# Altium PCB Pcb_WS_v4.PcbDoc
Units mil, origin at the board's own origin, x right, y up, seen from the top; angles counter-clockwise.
Board outline 3937.01 x 3937.01 mil, 2 copper layers (Top Layer, Bottom Layer); 75 components, 61 nets, 248 pads, 72 vias.
Unrouted connection lines stored in the file: 188.
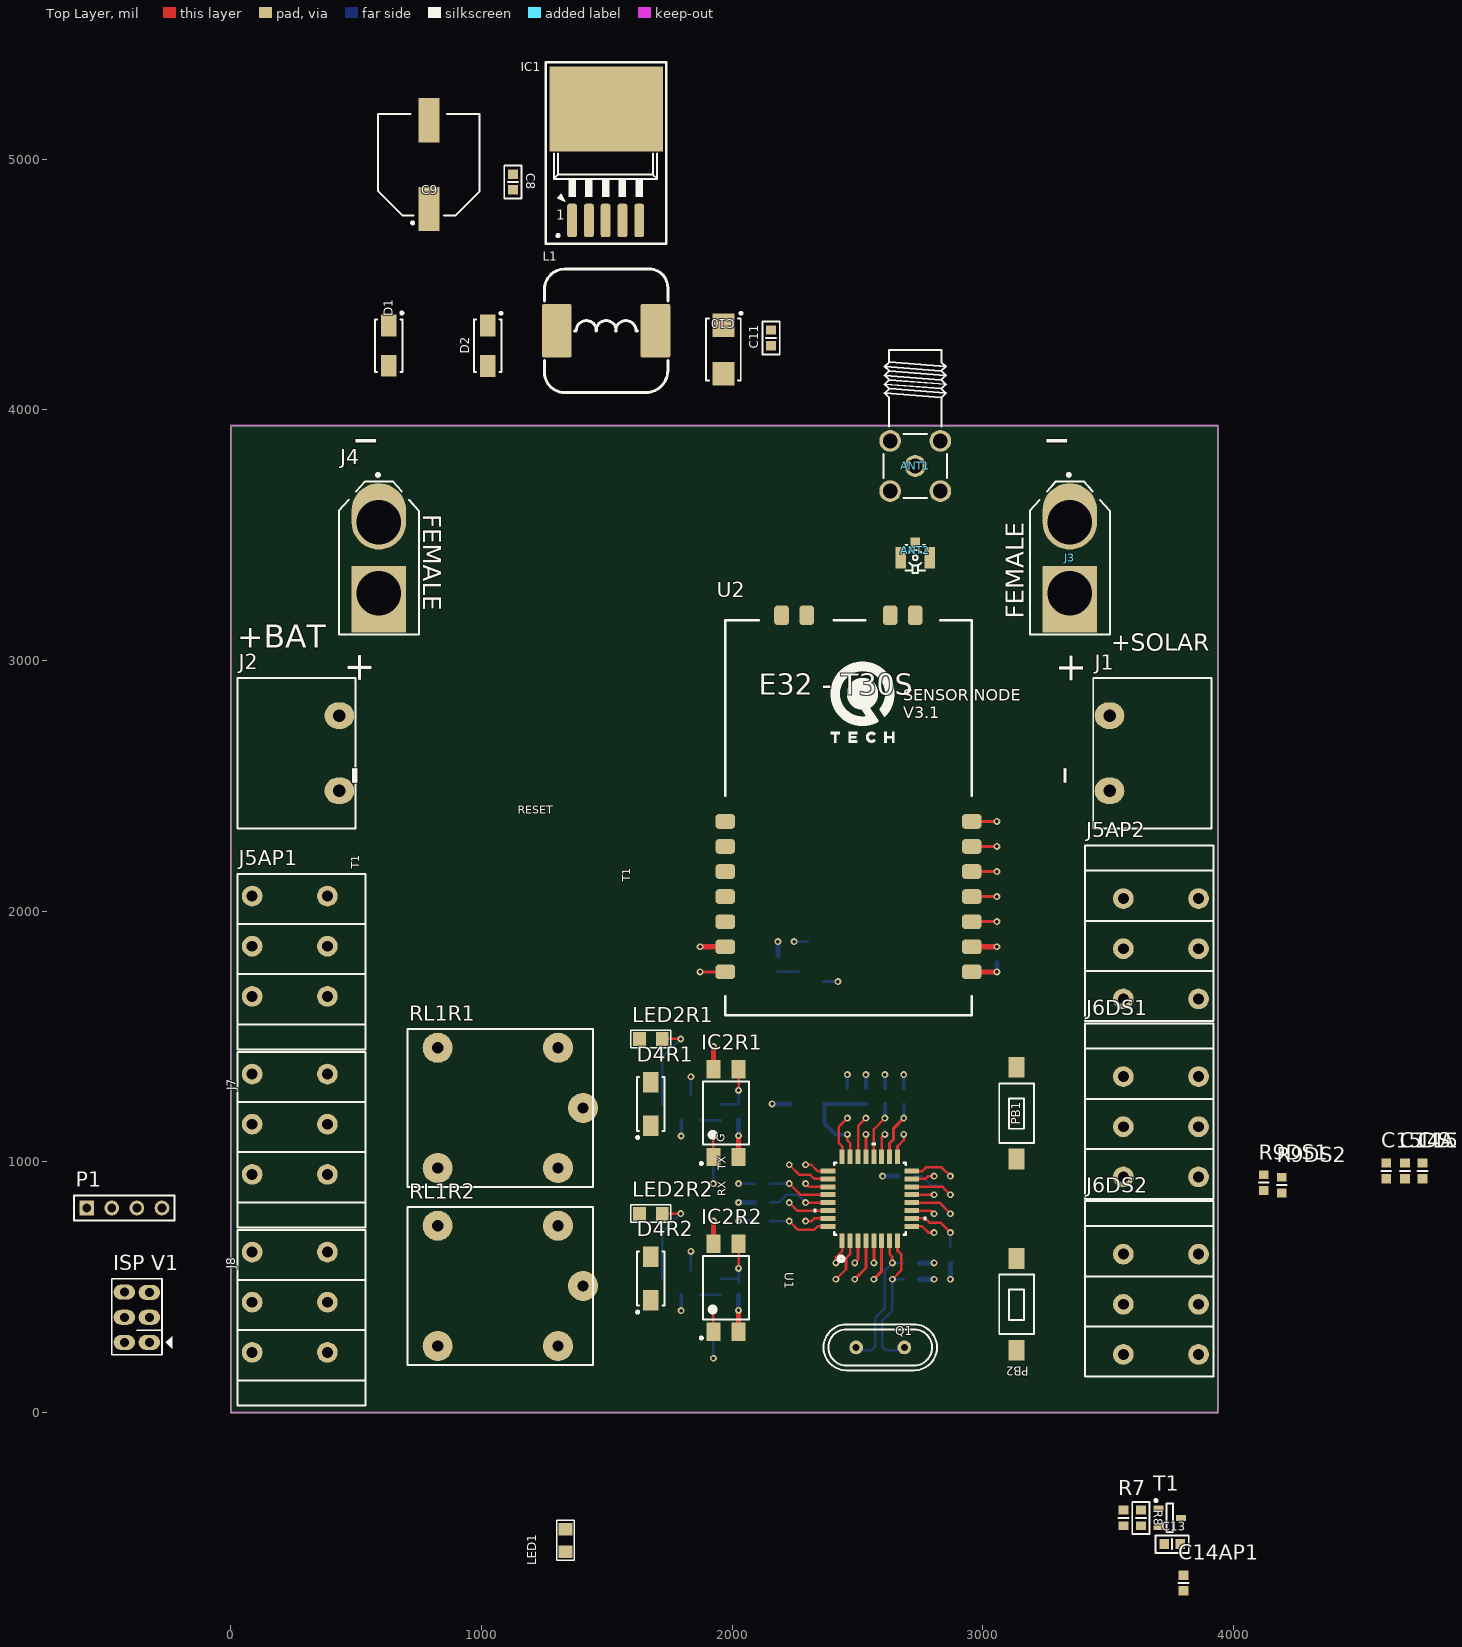
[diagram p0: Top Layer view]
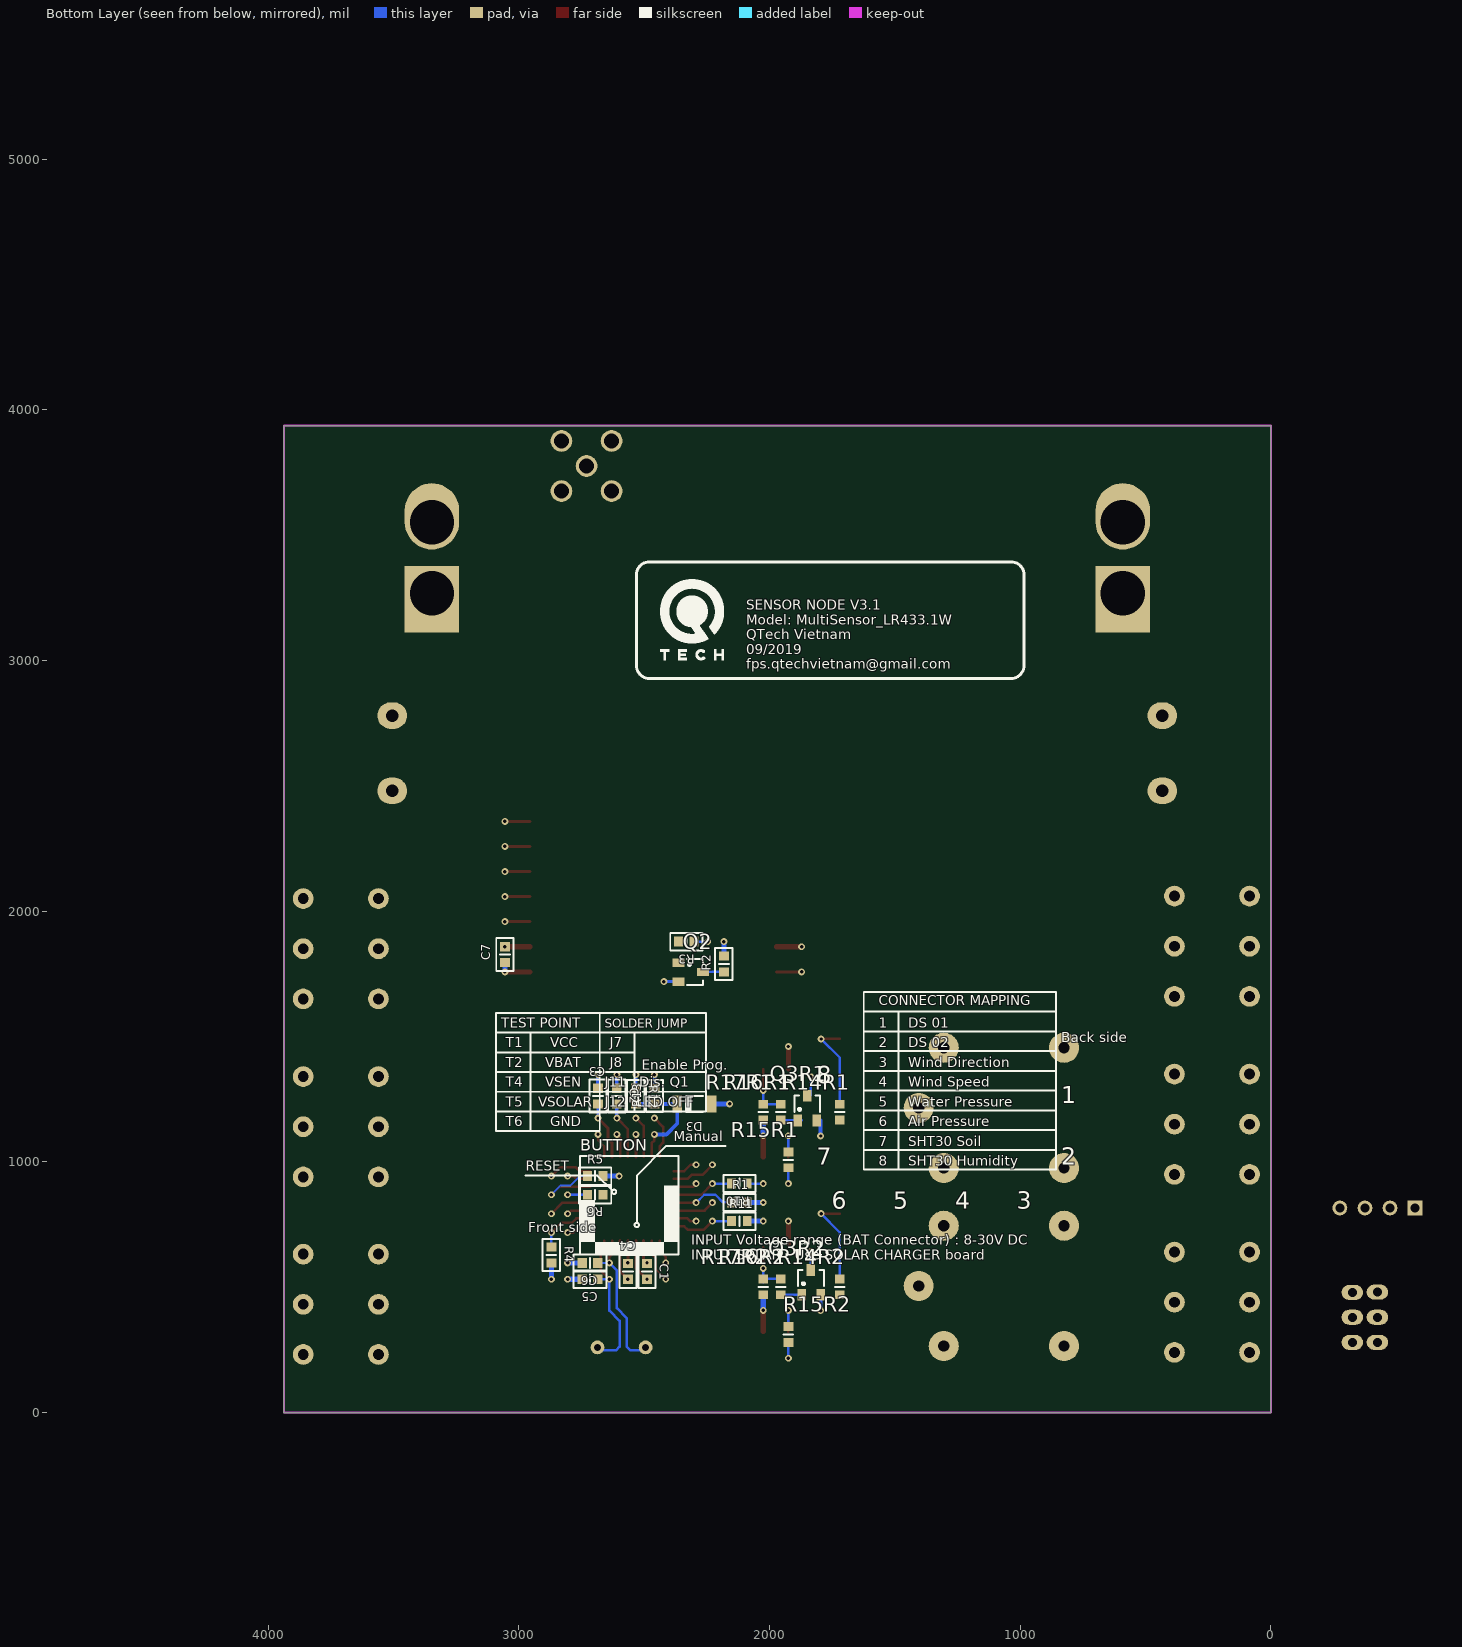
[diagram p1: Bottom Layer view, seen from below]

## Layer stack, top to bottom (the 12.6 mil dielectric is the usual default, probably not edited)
Top Solder: solder mask 0.4, Solder Resist, Dk 3.5
Top Layer: signal copper 1.4
Dielectric 1: dielectric 12.6, FR-4, Dk 4.8
Bottom Layer: signal copper 1.4
Bottom Solder: solder mask 0.4, Solder Resist, Dk 3.5

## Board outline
0,0 0,3937.01 3937.01,3937.01 3937.01,0

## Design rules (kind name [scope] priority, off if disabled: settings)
Clearance [All] p1: gap=7 ignorepadtopadclearanceinfootprint=FALSE
ComponentClearance KF-conn_Clearance [InComponentClass('KF_conn') vs InComponentClass('KF_conn')] p1: gap=5 collisioncheckmode=3 verticalgap=0 showdistances=FALSE
ComponentClearance HS_Comp_Clearance [InComponentClass('HS_Comp') vs IsComponent] p2: gap=175 collisioncheckmode=3 verticalgap=0 showdistances=FALSE
ComponentClearance IC_Comp_Clearance [InComponentClass('IC_Comp') vs IsComponent] p3: gap=150 collisioncheckmode=3 verticalgap=0 showdistances=FALSE
ComponentClearance conn-th_Clearance [InComponentClass('conn-th') vs IsComponent and not InComponentClass('conn-th')] p4: gap=150 collisioncheckmode=3 verticalgap=250 showdistances=FALSE
ComponentClearance chip-ge_Clearance [InComponentClass('chip-ge') vs InAnyComponent] p5: gap=100 collisioncheckmode=3 verticalgap=0 showdistances=FALSE
ComponentClearance chip-0603_Clearance [InComponentClass('chip-0603') vs IsComponent] p6: gap=25 collisioncheckmode=3 verticalgap=0 showdistances=FALSE
PolygonConnect [All] p1: thpad.connectstyle=Relief thpad.reliefconductorwidth=13.78 thpad.reliefentries=4 thpad.polygonreliefangle="45 Angle" thpad.airgapwidth=10 smdpad.connectstyle=Relief smdpad.reliefconductorwidth=11.81 smdpad.reliefentries=4 smdpad.polygonreliefangle="45 Angle" smdpad.airgapwidth=10 via.connectstyle=Direct via.reliefconductorwidth=10 via.reliefentries=4 via.polygonreliefangle="90 Angle" via.airgapwidth=10
RoomDefinition Top_Level [InComponentClass('Top_Level')] p1: confinementstyle=ConfineIn formatcopy=TRUE lockcomponents=FALSE outline -1380,-1215 620,-1215 620,-215 -1380,-215
RoomDefinition R2 [InComponentClass('R2')] p2: confinementstyle=ConfineIn formatcopy=TRUE lockcomponents=FALSE outline -1380,-1215 620,-1215 620,-215 -1380,-215
RoomDefinition R1 [InComponentClass('R1')] p3: confinementstyle=ConfineIn formatcopy=TRUE lockcomponents=FALSE outline -1380,-1215 620,-1215 620,-215 -1380,-215
RoomDefinition PWR [InComponentClass('PWR')] p4: confinementstyle=ConfineIn formatcopy=TRUE lockcomponents=FALSE outline -1380,-1215 620,-1215 620,-215 -1380,-215
RoomDefinition Main [InComponentClass('Main')] p5: confinementstyle=ConfineIn formatcopy=TRUE lockcomponents=FALSE outline -1380,-1215 620,-1215 620,-215 -1380,-215
RoomDefinition Lora [InComponentClass('Lora')] p6: confinementstyle=ConfineIn formatcopy=TRUE lockcomponents=FALSE outline -1380,-1215 620,-1215 620,-215 -1380,-215
RoomDefinition DS2 [InComponentClass('DS2')] p7: confinementstyle=ConfineIn formatcopy=TRUE lockcomponents=FALSE outline -1380,-1215 620,-1215 620,-215 -1380,-215
RoomDefinition DS1 [InComponentClass('DS1')] p8: confinementstyle=ConfineIn formatcopy=TRUE lockcomponents=FALSE outline -1380,-1215 620,-1215 620,-215 -1380,-215
RoomDefinition AP2 [InComponentClass('AP2')] p9: confinementstyle=ConfineIn formatcopy=TRUE lockcomponents=FALSE outline -1380,-1215 620,-1215 620,-215 -1380,-215
RoomDefinition AP1 [InComponentClass('AP1')] p10: confinementstyle=ConfineIn formatcopy=TRUE lockcomponents=FALSE outline -1380,-1215 620,-1215 620,-215 -1380,-215
RoutingVias [All] p1: holewidth=13.78 width=27.56 viastyle="Through Hole" minholewidth=11.81 minwidth=23.62 maxholewidth=19.68 maxwidth=39.37
ShortCircuit [All] p1: allowed=TRUE
SolderMaskExpansion [All] p1: expansion=4 istentingtop=FALSE
Width [All] p1: maxlimit=196.85 minlimit=8 preferedwidth=10
28 further rules are at their usual default settings.

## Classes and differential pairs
component class KF_conn: J5AP1 J5AP2 J6DS1 J6DS2 J7 J8
component class HS_Comp: ANT1 ANT2 Q1
component class IC_Comp: IC1 IC2R1 IC2R2 L1 U1 U2
component class chip-ge: C9 C10 D1 D2 D4R1 D4R2
component class conn-th: "ISP V1" J1 J2 J3 J4 J5AP1 J5AP2 J6DS1 J6DS2 J7 J8 P1 PB1 PB2 RL1R1 RL1R2
component class chip-0603: C1 C2 C3 C4 C5 C6 C7 C8 C11 C13 C14AP1 C14AP2 C15DS1 C15DS2 D3 LED1 LED2R1 LED2R2 Q2 Q3R1 Q3R2 R1 R2 R3 R4 R5 R6 R7 R8 R9DS1 R9DS2 R10 R11 R12 R13 R14R1 R14R2 R15R1 R15R2 R16R1 R16R2 R17R1 R17R2 T1
channel class Sensor_DS18b20_1Wire: DS1 DS2
channel class Sensor_AirPressure_1Wire: AP1 AP2
channel class Relay: R1 R2
component class Top_Level: D3 J7 J8 LED1 P1 PB2 R10 R11 R12 R13
component class R2: D4R2 IC2R2 LED2R2 Q3R2 R14R2 R15R2 R16R2 R17R2 RL1R2
component class R1: D4R1 IC2R1 LED2R1 Q3R1 R14R1 R15R1 R16R1 R17R1 RL1R1
component class Main: C1 C2 C3 C4 C5 C6 "ISP V1" PB1 Q1 R1 U1
component class Lora: ANT1 ANT2 C7 Q2 R2 R3 R4 R5 R6 U2
component class DS2: C15DS2 J6DS2 R9DS2
component class DS1: C15DS1 J6DS1 R9DS1
component class AP2: C14AP2 J5AP2
component class AP1: C14AP1 J5AP1
component class PWR: C8 C9 C10 C11 C13 D1 D2 IC1 J1 J2 J3 J4 L1 R7 R8 T1

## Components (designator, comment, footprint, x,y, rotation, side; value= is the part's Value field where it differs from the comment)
ANT1 "Coax_1Female_1Shield" "HUBER-SUHNER_85 SMA-50-0-101/111 NE" 2729.98,3775.65 r90 top
ANT2 "U.FL" HIROSE_U.FL-R-SMT-1(10) 2729.98,3409.96 r180 top
C1 "100nF" CAPC1608X87N 2488.75,563.14 r90 bottom
C2 "100nF" CAPC1608X87N 2609.14,1262.28 r270 bottom
C3 "100nF" CAPC1608X87N 2684.14,1262.28 r90 bottom
C4 "100nF" CAPC1608X87N 2564.69,563.14 r90 bottom
C5 "100nF" CAPC1608X87N 2715.95,531.64 r0 bottom value=22pF
C6 "100nF" CAPC1608X87N 2715.95,596.64 r0 bottom value=22pF
C7 "100nF" CAPC1608X87N 3055.57,1826.46 r270 bottom
C8 "100nF" CAPC1608X87N 1125,4908.5 r90 top
C9 "470uF" CAPAE1030X1020N 790,4977.84 r90 top
C10 "100uF" CAPMP6032X280N 1965,4240.24 r270 top
C11 "100nF" CAPC1608X87N 2155,4286.5 r270 top
C13 "100nF" CAPC1608X87N 3755,-524.96 r180 top
C14AP1 "100nF" CAPC1608X87N 3800,-680 r90 top (schematic designator C14)
C14AP2 "100nF" CAPC1608X87N 4684,964 r90 top (schematic designator C14)
C15DS1 "100nF" CAPC1608X87N 4609,964 r90 top (schematic designator C15)
C15DS2 "100nF" CAPC1608X87N 4754,964 r90 top (schematic designator C15)
D1 "SS16" DIOM5127X229N 630,4255.71 r270 top
D2 "SS16" DIOM5127X229N 1025,4255 r270 top
D3 "BZV55-B5V1" DIOMELF3515N 2299.1,1231 r180 bottom
D4R1 "BZG03C220" DIOM5326X230N 1675,1231 r90 top (schematic designator D4)
D4R2 "BZG03C220" DIOM5326X230N 1675,534.27 r90 top (schematic designator D4)
IC1 "LM2596" TO263-5 1361.14,4755 r0 top
IC2R1 "SFH6156-4" SOIC254P977X406-4N 1975,1194.47 r90 top (schematic designator IC2)
IC2R2 "SFH6156-4" SOIC254P977X406-4N 1975,497.74 r90 top (schematic designator IC2)
"ISP V1" "Connector 3x2" JP3x2 -375,380 r90 top
J1 "CON KF7.62-2P" "CON KF7.62-2P" 3505,2630 r270 top
J2 "CON KF7.62-2P" "CON KF7.62-2P" 433.07,2630 r90 top
J3 "XT60-FM" XT60-FM 3346.46,3409.45 r270 top locked
J4 "XT60-FM" XT60-FM 590.55,3409.45 r270 top locked
J5AP1 "KF142V-3P" "CON KF142V-3P-5.08" 85,2060 r270 top (schematic designator J5)
J5AP2 "KF142V-3P" "CON KF142V-3P-5.08" 3860,1650 r90 top (schematic designator J5)
J6DS1 "KF142V-3P" "CON KF142V-3P-5.08" 3860,940 r90 top (schematic designator J6)
J6DS2 "KF142V-3P" "CON KF142V-3P-5.08" 3860,231.72 r90 top (schematic designator J6)
J7 "KF142V-3P" "CON KF142V-3P-5.08" 85,1350 r270 top
J8 "KF142V-3P" "CON KF142V-3P-5.08" 85,640 r270 top
L1 "33uH" L_SMD 1300,4315 r90 top
LED1 "LED" L-0805 1335,-510 r270 top value="LED 3 ly Single Colour"
LED2R1 "LED" L-0805 1675,1490 r180 top value="LED 3 ly Single Colour" (schematic designator LED2)
LED2R2 "LED" L-0805 1675,793.27 r180 top value="LED 3 ly Single Colour" (schematic designator LED2)
P1 "Header 4" HDR1X4 -575,816 r0 top
PB1 "Push Button" PB_TYCO_FSMSM 3134,1194 r270 top
PB2 "Push Button" PB_TYCO_FSMSM 3134,431.72 r270 top
Q1 "20MHz" XTAL_HC-49/U 2590.35,259.85 r0 top
Q2 "C1815" SOT23-3 2314.31,1757.6 r270 bottom
Q3R1 "C1815" SOT23-3 1850,1214.47 r180 bottom (schematic designator Q3)
Q3R2 "C1815" SOT23-3 1835,518.77 r180 bottom (schematic designator Q3)
R1 "10k" RESC1608X55N 2120.35,837.85 r0 bottom
R2 "10k" RESC1608X55N 2182.1,1788.9 r90 bottom value=4k7
R3 "10k" RESC1608X55N 2332.02,1878.19 r0 bottom value=1k
R4 "10k" RESC1608X55N 2870.35,628.5 r90 bottom value=1k
R5 "4k7" RESC1608X55N 2695.31,942.85 r180 bottom value=10k
R6 "4k7" RESC1608X55N 2695.31,868.8 r180 bottom value=10k
R7 "1k" RESC1608X55N 3560,-420 r90 top
R8 "10k" RESC1608X55N 3630,-420 r90 top
R9DS1 "4k7" RESC1608X55N 4120,917 r90 top (schematic designator R9)
R9DS2 "4k7" RESC1608X55N 4192,907 r90 top (schematic designator R9)
R10 "10k" RESC1608X55N 2120.35,913.25 r180 bottom value=200
R11 "10k" RESC1608X55N 2120.35,763.25 r0 bottom
R12 "10k" RESC1608X55N 2533.2,1262.28 r270 bottom value=2M
R13 "10k" RESC1608X55N 2459.14,1262.28 r90 bottom value=1M
R14R1 "1k" RESC1608X55N 1720,1197.98 r90 bottom value=200 (schematic designator R14)
R14R2 "1k" RESC1608X55N 1720,501.24 r90 bottom value=200 (schematic designator R14)
R15R1 "1k" RESC1608X55N 1925,1007.98 r90 bottom (schematic designator R15)
R15R2 "1k" RESC1608X55N 1925,311.24 r90 bottom (schematic designator R15)
R16R1 "1k" RESC1608X55N 1955,1197.98 r270 bottom value=200 (schematic designator R16)
R16R2 "1k" RESC1608X55N 1955,501.24 r270 bottom value=200 (schematic designator R16)
R17R1 "10k" RESC1608X55N 2025,1197.98 r90 bottom (schematic designator R17)
R17R2 "10k" RESC1608X55N 2025,501.24 r90 bottom (schematic designator R17)
RL1R1 "Relay 10A/12V" RL_SPDT_10A 1405,1215 r180 top value="Relay SPDT, 10A, 12V" (schematic designator RL1)
RL1R2 "Relay 10A/12V" RL_SPDT_10A 1405,505 r180 top value="Relay SPDT, 10A, 12V" (schematic designator RL1)
T1 "BSH203" SOT95P230X110-3N 3745,-420 r0 top
U1 "ATmega328-AU" 32A_ATM-M 2548.95,853.05 r90 top
U2 "E32-T30S" E32-T30S 2955.57,3160.31 r180 top

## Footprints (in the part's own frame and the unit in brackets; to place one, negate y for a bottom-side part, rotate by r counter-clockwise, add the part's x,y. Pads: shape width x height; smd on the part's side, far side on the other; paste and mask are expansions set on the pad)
32A_ATM-M [mil]
  rect 58x20 smd: 1(-167,110.24) 2(-167,78.74) 3(-167,47.24) 4(-167,15.75) 5(-167,-15.75) 6(-167,-47.24) 7(-167,-78.74) 8(-167,-110.24) 17(167,-110.24) 18(167,-78.74) 19(167,-47.24) 20(167,-15.75) 21(167,15.75) 22(167,47.24) 23(167,78.74) 24(167,110.24)
  rect 20x58 smd: 9(-110.24,-167) 10(-78.74,-167) 11(-47.24,-167) 12(-15.75,-167) 13(15.75,-167) 14(47.24,-167) 15(78.74,-167) 16(110.24,-167) 25(110.24,167) 26(78.74,167) 27(47.24,167) 28(15.75,167) 29(-15.75,167) 30(-47.24,167) 31(-78.74,167) 32(-110.24,167)
  silkscreen extent -250,-224 224,224, body extent -182,-182 182,182, height 47
CAPAE1030X1020N [mm] "Capacitor, Aluminium Electrolytric, 10.3mm L X 10.3mm W X 10.2mm H, IPC Medium Density"
  rect 4.5x2.1 smd: 1(-4.5,0) 2(4.5,0)
  silkscreen extent -6.02,-5.15 5.15,5.15, body extent -6,-5.25 6,5.25, height 10.2
CAPC1608X87N [mm] "Chip Capacitor, Body 1.6x0.8mm IPC Medium Density"
  rect 0.95x1 smd: 1(-0.8,0) 2(0.8,0)
  silkscreen extent -1.68,-0.87 1.68,0.87, body extent -0.87,-0.47 0.88,0.48, height 0.87
CAPMP6032X280N [mm] "Capacitor, Polarized, Molded  Body 6.0x3.2mm, IPC Medium Density"
  rect 2.35x2.25 smd: 1(-2.45,0) 2(2.45,0)
  silkscreen extent -3.8,-1.75 3.15,1.9, body extent -3.15,-1.75 3.15,1.75, height 2.8
"CON KF7.62-2P" [mm]
  oval 2.7x3 hole 1.26: 1(-3.81,0) 2(3.81,0)
  silkscreen extent -7.62,-1.65 7.62,10.35, body extent -7.62,-1.65 7.62,10.35, height 12.4
"CON KF142V-3P-5.08" [mm]
  round 2.1 hole 1.1: 1(0,7.62) 1(0,0) 2(5.08,7.62) 2(5.08,0) 3(10.16,7.62) 3(10.16,0)
  silkscreen extent -2.25,-1.5 15.53,11.5, body extent -2.14,-1.57 15.54,11.63, height 14.23
DIOM5127X229N [mm] "DO-214-AC/SMA Molded Diode, 2-Leads, Body 5.1x2.7mm, IPC Medium Density"
  rect 2.2x1.55 smd: 1(-2.05,0) 2(2.05,0)
  silkscreen extent -3.42,-1.4 2.65,1.45, body extent -2.67,-1.45 2.68,1.45, height 2.29
DIOM5326X230N [mm] "DO-214-AC/SMA Molded Diode, Body 5.3x2.6mm, IPC Medium Density"
  rect 2.1x1.55 smd: 1(-2.2,0) 2(2.2,0)
  silkscreen extent -3.52,-1.4 2.75,1.45, body extent -2.75,-1.4 2.75,1.4, height 2.3
DIOMELF3515N [mm] "SOD80C, MELF Diode, 2-Leads, Body 3.5x1.5mm, IPC Medium Density"
  rect 1x1.75 smd: 1(-1.75,0) 2(1.75,0)
  silkscreen extent -0.85,-0.8 0.85,0.8, body extent -1.85,-0.8 1.85,0.8, height 1.6
E32-T30S [mm] "Lora-EBYTE-21~30dBm-UART-SX1278-25x40mm"
  rrect50% 2x1.5 smd: 1(0,20.38) 2(0,22.92) 3(0,25.46) 4(0,28) 5(0,30.54) 6(0,33.08) 7(0,35.62) 8(24.98,35.62) 9(24.98,33.08) 10(24.98,30.54) 11(24.98,28) 12(24.98,25.46) 13(24.98,22.92) 14(24.98,20.38)
  rrect50% 1.5x2 smd: 15(19.27,-0.5) 16(16.73,-0.5) 17(8.27,-0.5) 18(5.73,-0.5)
  silkscreen extent 0,0 25,40, body extent 0,0 25,40, height 3.5
HDR1X4 [mm] "Connector; Header; 4 Position"
  rect 1.5x1.5 hole 0.9: 1(0,0)
  round 1.5 hole 0.9: 2(2.54,0) 3(5.08,0) 4(7.62,0)
  silkscreen extent -1.27,-1.27 8.89,1.27
HIROSE_U.FL-R-SMT-1(10) [mm] "Up to 6GHz Ultra Small Surface Mount Male Coaxial Connectors U.FL Series"
  rect 1x1.05 smd: 1(0,-1.525)
  rect 1.05x2.2 smd: 2(-1.475,0) 2(1.475,0)
  silkscreen extent -1,-1.3 1,1.55, body extent -1.5,-1.55 1.5,1.55, height 1.25
"HUBER-SUHNER_85 SMA-50-0-101/111 NE" [mm] "50 Ohm SMA Right Angle PCB Jack"
  round 2.2 hole 1.5: 1(0,0) 2(-2.54,-2.54) 2(-2.54,2.54) 2(2.54,-2.54) 2(2.54,2.54)
  silkscreen extent -3.23,-3.23 11.73,3.23, body extent -3.23,-3.23 11.73,3.23, height 9.6
JP3x2 [mil] "Connector 3x2"
  oval 60x86 hole 36: 1(-100,-50) 2(0,-50) 3(99,-50) 4(-100,50) 5(0,50) 6(100,50)
  silkscreen extent -150,-141 154,100, body extent -150,-100 150,100, height 335
L-0805 [mil] "Compoment SMD 80x50mil"
  rect 50x55 smd: 1(-45,0) 2(45,0)
  silkscreen extent -80,-35 80,35, body extent -50,-20 50,20, height 43
L_SMD [mm]
  rrect10% 5.4x3 smd mask+0.1: 1(0,0) 2(0,-10)
  silkscreen extent -6.25,-11.25 6.25,1.25, body extent -6.25,-11.25 6.25,1.25, height 6.7
PB_TYCO_FSMSM [mm] "Body 3.5x6.0mm, Pushbutton Switch,  TYCO FSMSM Serie"
  rect 2.1x1.6 smd: 1(-4.65,0) 2(4.65,0)
  silkscreen extent -3,-1.75 3,1.75, body extent -5,-1.75 5,1.75, height 4.3
RESC1608X55N [mm] "Chip Resistor, EIA 0603, Metric 1608, Body 1.6x0.8mm, IPC Medium Density"
  rect 0.9x1 smd: 1(-0.8,0) 2(0.8,0)
  silkscreen extent -1.63,-0.87 1.63,0.87, body extent -0.87,-0.47 0.88,0.48, height 0.55
RL_SPDT_10A [mil] "Relay SPDT, 5 pin, 10A,W 650mil, L 800mil, H 800mil"
  round 120 hole 45: 1(0,0) 2(580,240) 3(580,-240) 4(100,-240) 5(100,240)
  silkscreen extent -40,-315 700,315
SOIC254P977X406-4N [mm] "SOIC, 2.54mm pitch; 4 pin, 6.65mm W X 4.69mm L, IPC Medium Density"
  rect 1.85x1.45 smd: 1(-4.45,1.27) 2(-4.45,-1.27) 3(4.45,-1.27) 4(4.45,1.27)
  silkscreen extent -5.22,-2.35 3.2,2.62, body extent -5.01,-2.41 5.02,2.42, height 4.06
SOT23-3 [mm] "SOT 23"
  rect 0.85x1.2 smd: 1(-0.94,-1.245) 2(0.985,-1.25) 3(0.005,1.25)
  silkscreen extent -1.29,-0.38 1.31,1.25, body extent -1.5,-1.5 1.52,1.5, height 1.27
SOT95P230X110-3N [mm] "SOT23, 3 pin, Pitch 0.95mm - 1.3mm W X 2.9mm L X 1.1mm H, IPC Medium Density"
  rect 1x0.6 smd: 1(-1.15,0.95) 2(-1.15,-0.95) 3(1.15,0)
  silkscreen extent -1.52,-1.45 0.33,1.87, body extent -1.17,-1.5 1.33,1.5, height 1.1
TO263-5 [mm]
  rrect50% 1x3.4 smd: 1(0,0) 2(1.7,0) 4(5.1,0) 5(6.8,0)
  rrect50% 1x3.4 smd mask+0: 3(3.4,0)
  rect 11.5x8.634 smd: 6(3.45,11.302)
  silkscreen extent -2.66,-2.38 9.54,16.02, body extent -1.71,-0.87 8.45,13.77, height 4.57
XT60-FM [mm]
  oval 6.716x5.516 hole 4.5 copper offset -0.6,0: 1(-3.6,0)
  rect 6.716x5.516 hole 4.5 copper offset 0.6,0: 2(3.6,0)
  silkscreen extent -8.55,-4.05 7.75,4.05, body extent -7.81,-4.07 8.12,4.06, height 15.5
XTAL_HC-49/U [mm] "HC-49/U Leaded Cristal, Body 11.05x4.8mm; Pitch 4.88mm"
  round 1.4 hole 0.7: 1(-2.44,0) 2(2.44,0)
  silkscreen extent -5.75,-2.33 5.75,2.33, body extent -5.75,-2.33 5.75,2.33, height 3.5

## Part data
ANT1: library part HUBER-SUHNER_85_SMA-50-0-101/111_NE, Manufacturer=HUBER+SUHNER, Manufacturer Part Number=85_SMA-50-0-101/111_NE
ANT2: library part HIROSE_U.FL-R-SMT-1(10), Manufacturer="HIROSE (HRS)", Manufacturer Part Number=U.FL-R-SMT-1(10)
C1 C2 C3 C4 C7 C8 C11 C13 C14AP1 C14AP2 C15DS1 C15DS2: library part CC0603_100NF_50V_10%_X7R, "Non-polarised capacitor", Case=0603, Manufacturer=GENERIC, Manufacturer1 ComponentHeight=0.87mm, Manufacturer1 Example=PHYCOMP, Manufacturer1 Part Number=223858615649, Tolerance=±10%, Voltage=50V
C5 C6: library part CC0603_22PF_50V_5%_NP0, "Non-polarised capacitor", Case=0603, Manufacturer=GENERIC, Manufacturer1 ComponentHeight=0.87mm, Manufacturer1 Example=PHYCOMP, Manufacturer1 Part Number=223886715229, Tolerance=±5%, Voltage=50V
C9: library part CAE1030-1020_470UF_25V_20%, "Polarised capacitor", Case=G, Manufacturer=GENERIC, Manufacturer1 ComponentHeight=10.2mm, Manufacturer1 Example=PANASONIC, Manufacturer1 Part Number=EEEFK1E471AP, Tolerance=±20%, Voltage=25V
C10: library part CTE6032-28_100UF_6.3V_10%_LESR0075, "Polarised capacitor", Case=C, Manufacturer=GENERIC, Manufacturer1 ComponentHeight=2.8mm, Manufacturer1 Example=AVX, Manufacturer1 Part Number=TPSC107K006R0075, Tolerance=±10%, Voltage=6.3V
D1 D2: "Schottky Diode", Case=DO-214AC, Manufacturer="VISHAY GENERAL SEMICONDUCTOR", Power=1A, Voltage=60V
D3: "Zener Diode", Case=SOD-80C, Manufacturer="NXP SEMICONDUCTORS", Power=500mW, Voltage=5V1
D4R1 D4R2: "Zener Diode", Case=DO-214AC, Manufacturer="VISHAY SEMICONDUCTOR", Power=1.25W, Voltage=220V
IC1: library part LM2596-5V
IC2R1 IC2R2: "Single Optocoupler", Case=SOIC4, Manufacturer="VISHAY SEMICONDUCTORS"
"ISP V1": library part JP3x2
J3 J4: Package="Package Analog Devices"
J5AP1 J5AP2 J6DS1 J6DS2 J7 J8: library part "CON KF142V-3P-5.08", "CON KF142V-3P-5.08"
L1: library part "L_SMD 33uH"
LED1 LED2R1 LED2R2: "LED Single colour Green and Red"
P1: "Header, 4-Pin"
PB1 PB2: "Push-Button Switch SPDT", Manufacturer="TYCO ELECTRONICS", Manufacturer Part Number="FSMSM or 1437566-3", Part Number=PB_TYCO_FSMSM
Q1: library part XTAL_20MHZ_AEL_HC-49/U, "Quartz Crystal", Manufacturer="AEL CRYSTALS", Manufacturer Part Number=X20M000000L010
Q2 Q3R1 Q3R2: library part 2SC1815, PSpiceTemplate="Q^@REFDES %c %b %e @MODEL"
R1 R5 R6 R8 R11 R17R1 R17R2: library part R0603_10K_1%_0.1W_100PPM, "Resistor - 1%", Case=0603, Manufacturer=GENERIC, Manufacturer1 ComponentHeight=0.55mm, Manufacturer1 Example="NIC COMPONENT", Manufacturer1 Part Number=NRC06F1002TRF, Power=0.1W, Tolerance=±1%
R2 R9DS1 R9DS2: library part R0603_4K7_1%_0.1W_100PPM, "Resistor - 1%", Case=0603, Manufacturer=GENERIC, Manufacturer1 ComponentHeight=0.55mm, Manufacturer1 Example="NIC COMPONENT", Manufacturer1 Part Number=NRC06F4701TRF, Power=0.1W, Tolerance=±1%
R3 R4 R7 R15R1 R15R2: library part R0603_1K_1%_0.1W_100PPM, "Resistor - 1%", Case=0603, Manufacturer=GENERIC, Manufacturer1 ComponentHeight=0.55mm, Manufacturer1 Example="NIC COMPONENT", Manufacturer1 Part Number=NRC06F1001TRF, Power=0.1W, Tolerance=±1%
R10 R14R1 R14R2 R16R1 R16R2: library part R0603_200R_1%_0.1W_100PPM, "Resistor - 1%", Case=0603, Manufacturer=GENERIC, Manufacturer1 ComponentHeight=0.55mm, Manufacturer1 Example="NIC COMPONENT", Manufacturer1 Part Number=NRC06F2000TRF, Power=0.1W, Tolerance=±1%
R12: library part R0603_2M_1%_0.1W_100PPM, "Resistor - 1%", Case=0603, Manufacturer=GENERIC, Manufacturer1 ComponentHeight=0.55mm, Manufacturer1 Example="NIC COMPONENT", Manufacturer1 Part Number=NRC06F2004TRF, Power=0.1W, Tolerance=±1%
R13: library part R0603_1M_1%_0.1W_100PPM, "Resistor - 1%", Case=0603, Manufacturer=GENERIC, Manufacturer1 ComponentHeight=0.55mm, Manufacturer1 Example="NIC COMPONENT", Manufacturer1 Part Number=NRC06F1004TRF, Power=0.1W, Tolerance=±1%
RL1R1 RL1R2: library part "Relay 1", "Relay SPDT,10A - 12VDC 5 Pin"
T1: "P-CHANNEL MOSFET WITH DIODE", Case=SOT23-3, Manufacturer="NXP SEMICONDUCTORS"
U1: "8-bit AVR Microcontroller, 32KB Flash, 1KB EEPROM, 2KB SRAM, 32-pin TQFP, Industrial Grade (-40°C to 85°C)", Supplier Part Number 1=ATMEGA328-AU-ND
U2: library part E32-433T30S, "Lora Ebyte E32-T30S Module"

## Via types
v1: diameter 27.56, hole 13.78, Top Layer to Bottom Layer, 72 vias

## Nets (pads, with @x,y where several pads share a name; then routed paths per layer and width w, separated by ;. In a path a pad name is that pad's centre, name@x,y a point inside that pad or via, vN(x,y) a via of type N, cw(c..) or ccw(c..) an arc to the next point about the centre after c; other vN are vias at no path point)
ANT_M: U2.18
ANT_M1: ANT1.1 ANT2.1
AREF: C2.2 U1.20 | length 229.1
  Top Layer w10: U1.20 2564.69,1130.01 v1(2609.14,1174.46)
  Bottom Layer w15: v1(2609.14,1174.46) C2.2
AUX: U1.2 U2.5 | length 277.8
  Top Layer w10: v1(2413.75,531.64) 2453.75,571.64 2453.75,615.27 2470.2,631.72 U1.2
  Top Layer w12: U2.5 v1(3055.57,1957.95)
BAT-VSEN: C8.1 C9.1 D1.1 IC1.1 R12.1 | length 54.1
  Bottom Layer w15: R12.1 v1(2533.2,1347.85)
BAT-VSEN-Q: D3.1 R12.2 R13.1 U1.23 | length 446.5
  Top Layer w10: v1(2459.14,1109.46) 2459.14,1085.44 2470.2,1074.38 U1.23
  Bottom Layer w15: v1(2459.14,1109.46) 2411.54,1109.46 2368,1153 D3.1 2368.22,1230.78 R13.1 R12.2
CLOSE1: J7.3 RL1R1.2
CLOSE2: J8.3 RL1R2.2
COM1: J7.2 RL1R1.1
COM2: J8.2 RL1R2.1
DATA-AP1: J5AP1.2 U1.24 | length 174.9
  Top Layer w10: U1.24 2438.71,1061.89 2424.14,1076.46 2424.14,1139.46 v1(2459.14,1174.46)
DATA-AP2: J5AP2.2 U1.25 | length 99.7
  Top Layer w10: v1(2292.54,988.25) 2315.14,988.25 2340.1,963.29 U1.25
DATA-DS1: J6DS1.2 R9DS1.1 U1.1 | length 99.7
  Top Layer w10: v1(2413.75,596.64) 2413.75,619.25 2438.71,644.21 U1.1
DATA-DS2: J6DS2.2 R9DS2.1 U1.9 | length 99.7
  Top Layer w10: U1.9 2757.79,742.82 2782.75,717.85 v1(2805.35,717.85)
GND: "ISP V1.5" ANT1.2 ANT2.2 C1.2 C2.1 C3.2 C4.2 C5.2 C6.2 C7.2 C8.2 C9.2 C10.2 C11.2 C13.2 C14AP1.1 C14AP2.1 C15DS1.1 C15DS2.1 D2.2 D3.2 IC1.3 IC1.5 IC1.6 IC2R1.2 IC2R2.2 J2.1 J4.1 J5AP1.3 J5AP2.3 J6DS1.3 J6DS2.3 LED1.2 P1.4 PB1.2 PB2.2 Q2.2 Q3R1.2 Q3R2.2 R4.1 R5.2 R6.2 R7.1 R13.2 R17R1.1 R17R2.1 U1.3 U1.5 U1.21 U2.7 U2.9 U2.15 U2.16 U2.17 | length 1467.9
  Top Layer w12: v1(2488.75,596.64) 2501.7,609.59 U1.3 ; U1.21 v1(2533.2,1109.46) ; v1(2564.69,596.64) U1.5
  Top Layer w20: v1(1872.1,1857.95) U2.9 ; IC2R2.2 v1(2025,407.35) ; IC2R1.2 v1(2025,1104.08) ; U2.7 v1(3055.57,1757.95)
  Bottom Layer w12: Q2.2 v1(2421.32,1718.8)
  Bottom Layer w15: v1(1796.2,406.32) Q3R2.2 ; v1(1796.2,1103.06) Q3R1.2@1796.2,1166.29 ; R13.2 v1(2459.14,1347.85) ; C2.1 v1(2609.14,1347.85) ; C3.2 v1(2684.14,1347.85)
  Bottom Layer w20: v1(2025,407.35) R17R2.1 ; v1(2025,1104.08) R17R1.1 ; v1(2158.9,1231) D3.2 ; v1(2599.95,942.85) R5.2 ; C5.2 v1(2805.35,531.64) ; C6.2 v1(2805.35,596.64) ; v1(2870.35,531.64) R4.1 ; v1(3055.57,1757.95) C7.2
GND-SOLAR: J1.2 J3.1
LED: R10.1 U1.28 | length 248.5
  Top Layer w10: v1(2227.54,913.25) 2271.98,868.8 U1.28
  Bottom Layer w10: R10.1 v1(2227.54,913.25)
M0: U1.11 U2.1 | length 194.8
  Top Layer w10: U1.11 2792.4,805.81 v1(2805.35,792.85)
  Top Layer w12: U2.1 v1(3055.57,2357.95)
M1: U1.12 U2.2 | length 272.8
  Top Layer w10: U1.12 2825.91,837.3 v1(2870.35,792.85)
  Top Layer w12: U2.2 v1(3055.57,2257.95)
MISO: "ISP V1.2" U1.16 | length 174.9
  Top Layer w10: U1.16 2757.79,963.29 2772.35,977.85 2835.35,977.85 v1(2870.35,942.85)
MOSI: "ISP V1.3" U1.15 | length 94
  Top Layer w10: U1.15 2770.27,931.79 2781.34,942.85 v1(2805.35,942.85)
NetD2_1: D2.1 IC1.2 L1.1
NetD4R1_2: D4R1.2 LED2R1.2 Q3R1.3 RL1R1.4 | length 74.6
  Bottom Layer w10: Q3R1.3@1834.8,1264.71 v1(1834.8,1339.27)
NetD4R2_2: D4R2.2 LED2R2.2 Q3R2.3 RL1R2.4 | length 74.6
  Bottom Layer w10: Q3R2.3 v1(1834.8,642.54)
NetIC2R1_1: IC2R1.1 R15R1.2 | length 149.4
  Top Layer w10: IC2R1.1 v1(1925,1104.08)
  Bottom Layer w10: R15R1.2 v1(1925,1104.08)
NetIC2R2_1: IC2R2.1 R15R2.2 | length 149.4
  Top Layer w10: IC2R2.1 v1(1925,407.35)
  Bottom Layer w10: R15R2.2 v1(1925,407.35)
NetLED1_1: LED1.1 R10.2 | length 63.9
  Bottom Layer w10: v1(2025,913.25) R10.2
NetLED2R1_1: LED2R1.1 R14R1.2 | length 366
  Top Layer w10: LED2R1.1 v1(1794.55,1490)
  Bottom Layer w10: R14R1.2 1720,1415.45 v1(1794.55,1490)
NetLED2R2_1: LED2R2.1 R14R2.2 | length 366
  Top Layer w10: LED2R2.1 v1(1794.55,793.27)
  Bottom Layer w10: R14R2.2 1720,718.71 v1(1794.55,793.27)
NetQ2_1: Q2.1 R3.2
NetQ3R1_1: Q3R1.1 R16R1.2 | length 83
  Bottom Layer w10: Q3R1.1@1872.02,1166.48 R16R1.2
NetQ3R2_1: Q3R2.1 R16R2.2 | length 83
  Bottom Layer w10: Q3R2.1@1872.02,469.75 R16R2.2
NetR7_2: R7.2 R8.2 T1.1
NetU1_19: U1.19 | length 94.8
  Top Layer w10: U1.19 2596.19,1096.51 v1(2609.14,1109.46)
NetU1_22: U1.22 | length 167.5
  Top Layer w10: U1.22 2501.7,1142.96 v1(2533.2,1174.46)
NetU2_10: U2.10
NetU2_11: U2.11
NetU2_12: U2.12
NetU2_13: U2.13
NetU2_14: U2.14
OPEN1: J7.1 RL1R1.3
OPEN2: J8.1 RL1R2.3
P5V-Main: "ISP V1.6" C1.1 C3.1 C4.1 C7.1 C10.1 C11.1 D4R1.1 D4R2.1 IC1.4 IC2R1.4 IC2R2.4 L1.2 P1.1 R1.1 R2.2 R8.1 R11.1 R14R1.1 R14R2.1 RL1R1.5 RL1R2.5 T1.2 U1.4 U1.6 U1.18 U2.6 | length 1040.6
  Top Layer w12: v1(2488.75,531.64) 2533.2,576.09 U1.4 ; v1(2564.69,531.64) 2596.19,563.14 U1.6 ; U1.18 2627.69,1074.38 2644.14,1090.84 2644.14,1134.46 v1(2684.14,1174.46)
  Top Layer w20: IC2R2.4 v1(1925,763.27) ; IC2R1.4 v1(1925,1460) ; U2.6 v1(3055.57,1857.95)
  Bottom Layer w12: v1(2684.14,1174.46) C3.1
  Bottom Layer w20: v1(2025,763.25) R11.1 ; v1(2025,837.85) R1.1 ; R2.2 v1(2182.1,1878.19)
P5V-SEN: C13.1 C14AP1.2 C14AP2.2 C15DS1.2 C15DS2.2 J5AP1.1 J5AP2.1 J6DS1.1 J6DS2.1 R9DS1.2 R9DS2.2 T1.3
P12V-BAT: D1.2 J2.2 J4.2
P16V-SOLAR: J1.1 J3.2
RESET-E32: R3.1 R4.2 U1.10 | length 289.7
  Top Layer w10: U1.10 2770.27,774.31 2786.73,757.85 2830.35,757.85 v1(2870.35,717.85)
  Bottom Layer w9.84: v1(2246.45,1878.19) R3.1
  Bottom Layer w10: R4.2 v1(2870.35,717.85)
RL-CT-QR1: IC2R1.3 R16R1.1 R17R1.2 | length 210.2
  Top Layer w10: v1(2025,1284.87) IC2R1.3
  Bottom Layer w10: R16R1.1 R17R1.2 v1(2025,1284.87)
RL-CT-QR2: IC2R2.3 R16R2.1 R17R2.2 | length 210.2
  Top Layer w10: v1(2025,574.87) IC2R2.3@2025,659.67
  Bottom Layer w10: R16R2.1 R17R2.2 ; R17R2.2@2025,519.47 v1(2025,574.87)
RL-CTL1: R15R1.1 U1.26 | length 241
  Top Layer w10: v1(2227.54,988.25) 2267.54,948.25 2311.16,948.25 2327.62,931.79 U1.26
  Bottom Layer w10: v1(1925,913.25) R15R1.1
RL-CTL2: R15R2.1 U1.27 | length 158
  Top Layer w10: v1(2292.54,913.25) 2305.49,900.3 U1.27
  Bottom Layer w10: v1(1925,216.52) R15R2.1
RST-E32: Q2.3 R2.1 U2.8 | length 183
  Top Layer w12: v1(1872.1,1757.95) U2.8
  Bottom Layer w10: R2.1 Q2.3
RST_MCU: "ISP V1.4" PB1.1 R1.2 U1.29 | length 256
  Top Layer w10: v1(2292.54,837.3) U1.29
  Bottom Layer w10: R1.2 2185.35,837.85 2216.3,868.8 2260.35,868.8 2291.85,837.3 v1(2292.54,837.3)
RXD-E32: R6.1 U1.13 U2.3 | length 268
  Top Layer w10: U1.13 v1(2805.35,868.8)
  Top Layer w12: U2.3 v1(3055.57,2157.95)
  Bottom Layer w10: R6.1 v1(2805.35,868.8)
RXM: P1.3 U1.30 | length 167.5
  Top Layer w10: v1(2227.54,837.3) 2259.03,805.81 U1.30
SCK: "ISP V1.1" U1.17 | length 99.7
  Top Layer w10: U1.17 2659.18,1061.89 2684.14,1086.85 v1(2684.14,1109.46)
TXD-E32: R5.1 U1.14 U2.4 | length 441.7
  Top Layer w10: U1.14 2838.86,900.3 v1(2870.35,868.8)
  Top Layer w12: U2.4 v1(3055.57,2057.95)
  Bottom Layer w8: R5.1 2757.45,942.85 2795.31,905 2834.15,905 v1(2870.35,868.8)
TXM: P1.2 U1.31 | length 94
  Top Layer w10: v1(2292.54,763.25) 2316.55,763.25 2327.62,774.31 U1.31
WAKE: PB2.1 R11.2 U1.32 | length 250.6
  Top Layer w10: v1(2227.54,763.25) 2262.54,728.25 2325.54,728.25 2340.1,742.82 U1.32
  Bottom Layer w10: R11.2 v1(2227.54,763.25)
XTAL1: C6.1 Q1.1 U1.7 | length 583.8
  Top Layer w10: U1.7 2627.69,631.72 2638.75,620.66 v1(2638.75,596.64)
  Bottom Layer w8: v1(2638.75,596.64) C6.1
  Bottom Layer w10: Q1.1@2494.29,247.85 2554.85,247.85 2569.85,262.85 2569.85,376.95 2609.14,416.24 2609.14,567.04 v1(2638.75,596.64)
XTAL2: C5.1 Q1.2 U1.8 | length 601.1
  Top Layer w10: v1(2638.75,531.64) 2673.75,566.64 2673.75,631.72 2659.18,646.29 U1.8
  Bottom Layer w10: C5.1 v1(2638.75,531.64) 2638.75,406.25 2597.85,365.35 2597.85,262.85 2612.85,247.85 Q1.2@2686.42,247.85

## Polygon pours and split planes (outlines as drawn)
no net on Top Layer "AutoNaming" (solid, pour order 26): 0,170
no net on Top Layer "AutoNaming" (solid, pour order 22): 0,170
no net on Top Layer "Top Layer-No Net" (solid, pour order 14): 1172.91,4781.41

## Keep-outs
Keep-Out Layer:
  the board outline again, w7.87

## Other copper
Top Layer:
  region: 991.15,1125.57
  pour cut-out: 3949.69,1440.41
  pour cut-out: 3949.69,1440.41
  region: 340,2910

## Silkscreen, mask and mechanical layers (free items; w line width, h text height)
Top Overlay:
  drawing of 802 lines, arcs and shapes, not listed
  text "-" at 482.28,3720.47 h393.7
  text "-" at 3238.19,3720.47 h393.7
  text "FEMALE" at 767.72,3582.48 h70.87 r270
  text "FEMALE" at 3162.72,3165.48 h70.87 r90
  text "+BAT" at 26,3018 h157.48
  text "+SOLAR" at 3511,3015 h118.11
  text "+" at 600.39,2904.11 h196.85 r90
  text "+" at 3438.98,2903.54 h196.85 r90
  text "SENSOR NODE / V3.1" at 2682.41,2769.24 h47.24
  text "-" at 600.39,2500 h275.59 r90
  text "-" at 610.24,2500 h275.59 r90
  text "-" at 3438.98,2500 h275.59 r90
  text "RESET" at 1145.39,2388.26 h31.5
  text "T1" at 511.83,2168.48 h31.5 r90
  text "T1" at 1594,2116.39 h31.5 r90
  text "G" at 1970.39,1078.39 h31.5 r90
  text "TX" at 1973.39,967.39 h31.5 r90
  text "RX" at 1973.39,863.39 h31.5 r90
Bottom Overlay:
  drawing of 873 lines, arcs and shapes, not listed
  text "SENSOR NODE V3.1 / Model: MultiSensor_LR433.1W / QTech Vietnam / 09/2019 / fps.qtechvietnam@gmail.com" at 2092.27,2966.11 h39.37
  text "CONNECTOR MAPPING" at 1565.09,1624.02 h39.37
  text "DS 01" at 1446.98,1535.43 h39.37
  text "1" at 1564.96,1535.43 h39.37
  text "SOLDER JUMP" at 2657.48,1535.43 h35.43
  text "TEST POINT" at 3070.87,1535.43 h39.37
  text "Back side" at 836.61,1476.38 h39.37
  text "DS 02" at 1446.98,1456.69 h39.37
  text "2" at 1564.96,1456.69 h39.37
  text "J7" at 2637.8,1456.69 h39.37
  text "VCC" at 2874.02,1456.69 h39.37
  text "T1" at 3051.18,1456.69 h39.37
  text "Wind Direction" at 1446.98,1377.95 h39.37
  text "3" at 1565.09,1377.95 h39.37
  text "J8" at 2637.8,1377.95 h39.37
  text "VBAT" at 2893.7,1377.95 h39.37
  text "T2" at 3051.18,1377.95 h39.37
  text "Enable Prog." at 2509.84,1368.11 h39.37
  text "Wind Speed" at 1446.98,1299.21 h39.37
  text "4" at 1565.09,1299.21 h39.37
  text "Dis. Q1" at 2519.68,1299.21 h39.37
  text "J11" at 2657.48,1299.21 h39.37
  text "VSEN" at 2893.7,1299.21 h39.37
  text "T4" at 3051.18,1299.21 h39.37
  text "8" at 1811.15,1289.37 h118.11
  text "Water Pressure" at 1446.98,1220.47 h39.37
  text "5" at 1565.09,1220.47 h39.37
  text "LED OFF" at 2529.53,1220.47 h39.37
  text "J12" at 2657.48,1220.47 h39.37
  text "VSOLAR" at 2923.23,1220.47 h39.37
  text "T5" at 3051.18,1220.47 h39.37
  text "1" at 836.74,1210.63 h118.11
  text "Air Pressure" at 1446.98,1141.73 h39.37
  text "6" at 1565.09,1141.73 h39.37
  text "GND" at 2874.02,1141.73 h39.37
  text "T6" at 3051.18,1141.73 h39.37
  text "Manual" at 2382.02,1083.06 h39.37
  text "SHT30 Soil" at 1446.98,1062.99 h39.37
  text "7" at 1565.09,1062.99 h39.37
  text "BUTTON" at 2755.91,1043.31 h47.24
  text "SHT30 Humidity" at 1446.98,984.25 h39.37
  text "8" at 1565.09,984.25 h39.37
  text "2" at 836.74,964.57 h118.11
  text "7" at 1811.15,964.57 h118.11
  text "RESET" at 2972.44,964.57 h39.37
  text "3" at 1013.91,789.45 h118.11
  text "4" at 1259.97,789.45 h118.11
  text "5" at 1506.03,789.45 h118.11
  text "6" at 1752.09,789.45 h118.11
  text "Front side" at 2962.6,718.5 h39.37
  text "INPUT Voltage range (BAT Connector) : 8-30V DC / INPUT SOLAR : Use SOLAR CHARGER board" at 2312.99,610.24 h39.37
